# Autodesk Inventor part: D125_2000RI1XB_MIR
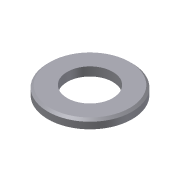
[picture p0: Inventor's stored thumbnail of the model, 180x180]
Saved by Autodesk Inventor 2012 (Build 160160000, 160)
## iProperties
Company: CAD-Verlag
Shininess: 64.0
Length Units: 11269
Angle Units: 11279
Time Units: 11290
Mass Units: 11283
Length Display Precision: 3
Angle Display Precision: 2
Compacted: True
Part Number: D125_2000RI1XB_MIR
Document SubType Name: Modeling
Created: 2004-09
Material: Steel, Mild
Designer: Greiling
Manufacturer: Standard
Standards Organization: Custom
Density: 1 g/cm^3
Density: 0.0
Volumn: 0.0
Area: 0.0
PropertySet Name: Model Information
Control State: 0
Master: False
Checked Out: False
d16: 0,000 mm
Author: Jürgen Kronas
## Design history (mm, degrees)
node "Unterlegscheibe DIN 125-B12" dims "d0" = 10, "d16" = 0
  node "WorkPlane1"
  node "WorkPlane3"
  node "MSC_PT1"
  node "MSC_PT2"
  node "WorkAxis1"
  node "MSC_A1"
  node "WorkPoint2"
  node "WorkPoint1"
node "Volumenkörper1"
node "Volumenkörpern"
node "Oberflächenkörpern"
tag "Bezeichnung2"
feature "Volumenkörper1::Unterlegscheibe DIN 125-B12" dims "d0" = 10, "d16" = 0
